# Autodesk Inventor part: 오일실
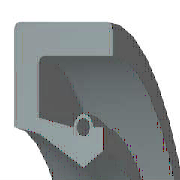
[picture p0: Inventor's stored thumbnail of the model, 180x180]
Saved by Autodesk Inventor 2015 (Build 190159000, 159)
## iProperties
IsCustomPart: 1
Created: 2015-12
Part Number: 오일실
Material: 고무
Description: 오일-실
Document SubType Name: Modeling
Standard: KS B 2804
Designer: mdu
Standards Organization: KS
Language: ko-KR
Size Designation: S - 15 30 7
Categories: <MemberInstance><Categories><Category DisplayName="샤프트 부품" InternalName="7f7aeb1f-a693-4053-b835-cee3144e0d98" Mnemonic="SHFT"><Category DisplayName="실링" Intern
Density: 0.93 g/cm^3
Appearance: 고무 - 검은색 - 버전 1.1
Mass: 1.64364 g
Surface Area: 26.6454 cm^2
Volume: 1.76736 cm^3
Author: mdu
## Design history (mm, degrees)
revolve "본체" stored, may be unused: angle "d17" = 90 deg
revolve "스프링1" stored, may be unused: angle "d18" = 90 deg
body "Solid1"
sketch "스케치1"
  geometry: L1 (0, 15)-(7, 15); L2 (7, 15)-(7, 13.75); L3 (7, 13.75)-(1.75, 13.75); L4 (0, 15)-(0, 9.6); L5 (0, 9.6)-(1.75, 9.25); L6 (1.75, 9.25)-(4.9, 7.5); L7 (4.9, 7.5)-(0, 7.5); L8 (6.3, 8.375)-(6.3, 9.6); L9 (0, 0)-(9.586, 0) reference; L10 (4.9, 7.5)-(6.3, 8.375); L11 (0, 18)-(0, -3) reference; L12 (-1.917, 0)-(11.503, 0) reference; L13 (4.2, 9.6)-(1.75, 10.09); L14 (1.75, 10.09)-(1.75, 13.75); L15 (6.3, 9.6)-(5.6, 9.6); C1 r 0.455 at (4.9, 9.6); A1 r 0.7 centre (4.9, 9.6) between (5.6, 9.6) and (4.2, 9.6)
  constraints: 26 end point, 5 horizontal alignment, 4 perpendicular, 2 centre point, 2 collinear, 2 horizontal, 2 parallel, 2 point on circle, 2 point on line, 2 vertical alignment, 1 coincident
  dimensions: "d0" = 30 diameter of L1 L9 (= SD2); "d1" = 16.75 diameter of L8.start L9 (= ABDM); "d2" = 1.25 distance of L1.end L2.end (computed from SD); "d3" = 0.91 diameter of C1 (= SPDI); "d4" = 1.4 diameter of A1 (= SPDA); "d5" = 15 diameter of L6.end L9 (= NND); "d6" = 18.5 diameter of L5.end L9 (= TKDM); "d7" = 19.2 diameter of L4.end L9 (= HLDM); "d8" = 4.9 distance from line of C1.centre L4 (= SPDST); "d9" = 6.3 distance between parallel lines of L8 L4 (= SDI); "d10" = 7 distance between parallel lines of L2 L4 (= SWDT); "d12" = 1.75 distance between parallel lines of L14 L4 (= SD)
fillet "모깎기1" dims "d11" = 0.3 (= RR)
other parameters: "SD2" = 30 [user parameter; used in 1 equation term], "SWDT" = 7 [user parameter; used in 1 equation term], "RR" = 0.3 [user parameter; used in 1 equation term], "SD" = 1.75 [user parameter; used in 2 equation terms], "NND" = 15 [user parameter; used in 1 equation term], "SPDA" = 1.4 [user parameter; used in 1 equation term], "SPDI" = 0.91 [user parameter; used in 1 equation term], "TKDM" = 18.5 [user parameter; used in 1 equation term], "HLDM" = 19.2 [user parameter; used in 1 equation term], "ABDM" = 16.75 [user parameter; used in 1 equation term], "SDI" = 6.3 [user parameter; used in 1 equation term], "SPDST" = 4.9 [user parameter; used in 1 equation term], "d13" = 0, "d14" = 0, "d15" = 0, "LAB" = 0.35 [user parameter]
